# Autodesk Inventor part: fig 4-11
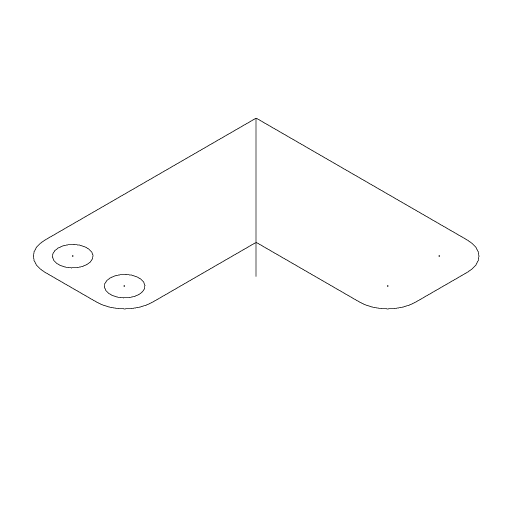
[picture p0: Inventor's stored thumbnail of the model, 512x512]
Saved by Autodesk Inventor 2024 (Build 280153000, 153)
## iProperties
Created: 2005-02
Part Number: fig 4-11
Document SubType Name: Modeling
Designer: CADCIM
Manufacturer: Standard
Standards Organization: Custom
Density: 1 g/cm^3
Material: Generic
Appearance: Default
Author: CADCIM
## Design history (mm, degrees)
sketch "Sketch1"
  geometry: L1 (5.141, 24.979)-(-32.827, 24.979); L2 (-32.827, 24.979)-(-32.827, -12.989); L3 (-27.827, -17.989)-(-18.492, -17.989); L4 (-13.492, -12.989)-(-13.492, 5.644); L5 (-13.492, 5.644)-(5.141, 5.644); L6 (10.141, 10.644)-(10.141, 19.979); L7 (-32.827, 24.979)-(-8.203, 0.354); C1 r 2.58 at (-27.827, -12.989); C2 r 2.58 at (-18.492, -12.989); A1 r 5 centre (-27.827, -12.989) between (-32.827, -12.989) and (-27.827, -17.989); A2 r 5 centre (-18.492, -12.989) between (-18.492, -17.989) and (-13.492, -12.989); A3 r 5 centre (5.141, 10.644) between (5.141, 5.644) and (10.141, 10.644); A4 r 5 centre (5.141, 19.979) between (10.141, 19.979) and (5.141, 24.979)
  constraints: 14 end point, 8 point on circle, 8 tangent, 6 centre point, 4 equal radius, 4 parallel, 3 perpendicular, 2 coincident, 1 horizontal, 1 point on line
